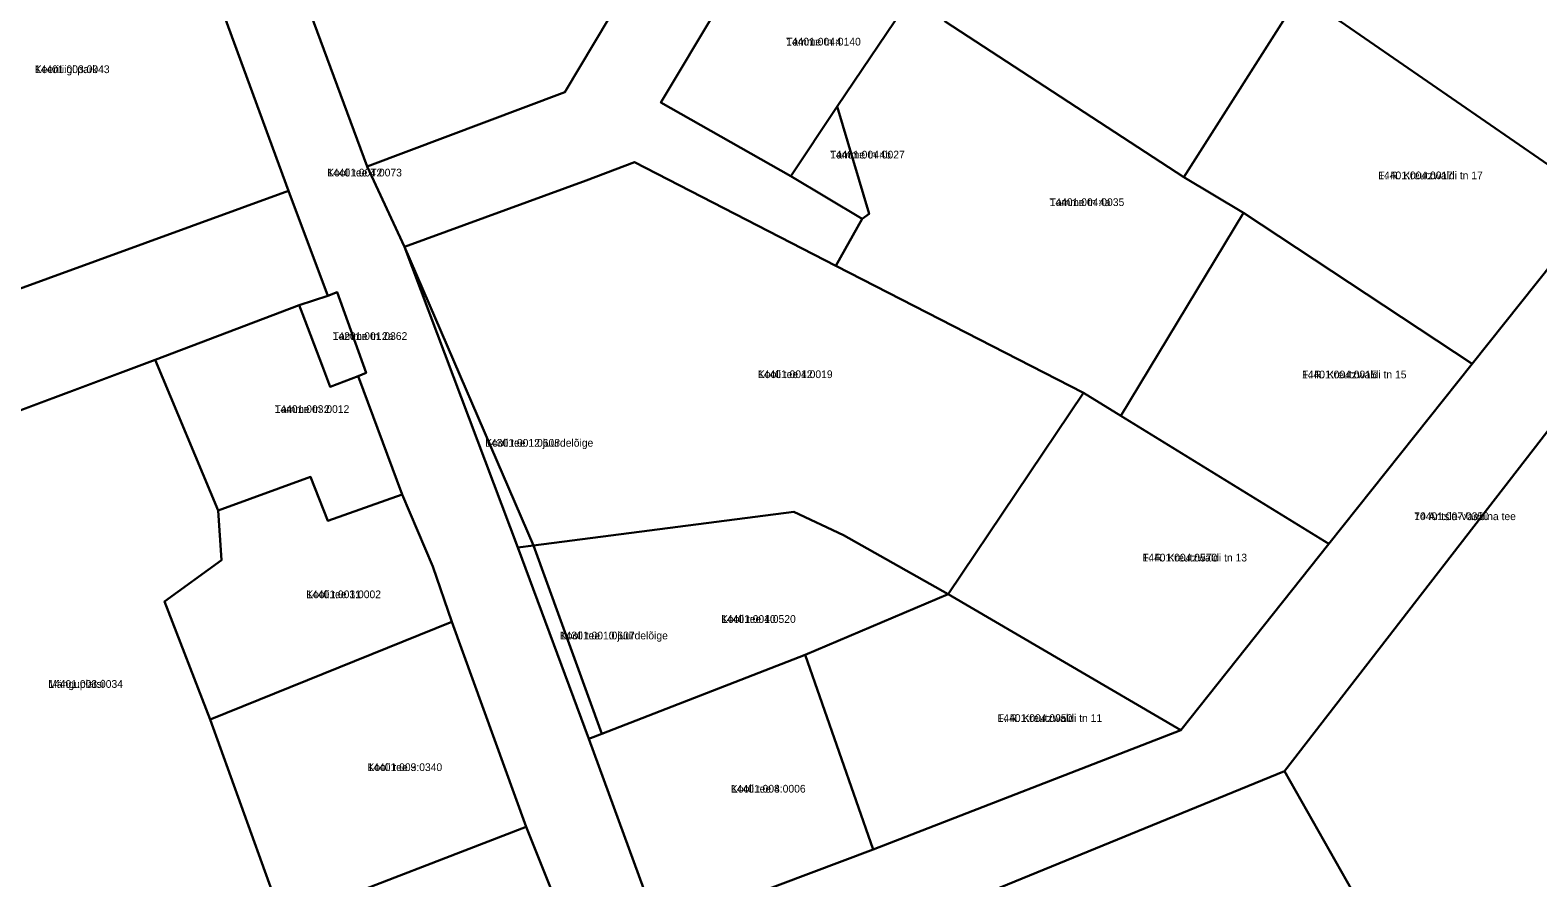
# Model space of a CAD drawing. Extents: x 640657 to 665127, y 6395726 to 6426831.
# Drawn here: x 650279.6 to 650572.3, y 6412630.2 to 6412794.8 of the extents above; entities that cross this region are included whole.
import ezdxf

# ---------------------------------------------------------------- set-up
doc = ezdxf.new("R2010")
doc.units = 0
for name, color, linetype in [('L_AADRESS', 7, 'Continuous'), ('PIIR', 7, 'Continuous'), ('TUNNUS', 7, 'Continuous')]:
    doc.layers.add(name, color=color, linetype=linetype)

msp = doc.modelspace()

# ---------------------------------------------------------------- linework, layer by layer
at = {"layer": 'PIIR'}
for points in [[(650401.68, 6412620.02), (650443.31, 6412635.66), (650502.99, 6412658.87), (650531.76, 6412695.05), (650559.55, 6412729.99), (650584.65, 6412761.55), (650611.45, 6412796.26), (650628.07, 6412817.98), (650642.14, 6412836.53), (650659.43, 6412858.77), (650671.35, 6412873.26), (650691.08, 6412899.24), (650704.96, 6412917.1), (650717.93, 6412933.8), (650741.65, 6412963.62), (650765.03, 6412993.85), (650786.55, 6413021.63), (650809.09, 6413051.96), (650817.6, 6413061.15)], [(650817.7, 6413031.91), (650806.76, 6413017.69), (650784.43, 6412989.36), (650760.68, 6412958.63), (650735.21, 6412925.98), (650707.5, 6412890.28), (650682.06, 6412857.34), (650670.16, 6412841.93), (650650.26, 6412816.25), (650622.9, 6412780.36), (650600.95, 6412752.04), (650584, 6412729.6), (650523.13, 6412650.87), (650462.26, 6412625.96)], [(650278.55, 6412923.91), (650292.03, 6412907.35), (650296.86, 6412894.32), (650296.86, 6412889.11), (650305.95, 6412866.72), (650311.87, 6412858.01), (650345.05, 6412768.31), (650352.3, 6412752.69), (650374.32, 6412694.32), (650388.11, 6412657.18), (650401.68, 6412620.02)], [(650386.32, 6412614.06), (650375.93, 6412640.11), (650361.5, 6412679.88), (650357.8, 6412690.63), (650351.84, 6412704.65), (650343.32, 6412727.61), (650344.83, 6412728.23), (650339.2, 6412743.9), (650337.4, 6412743.2), (650329.8, 6412763.6), (650299.3, 6412846.7), (650285.9, 6412881.2), (650282.26, 6412886.17), (650272.9, 6412909.24)], [(650424.35, 6412817.94), (650402.06, 6412780.76), (650427.29, 6412766.46), (650441.14, 6412758.16), (650436.06, 6412749.03), (650396.96, 6412769.19), (650387.58, 6412765.59), (650352.3, 6412752.69), (650345.05, 6412768.31), (650383.45, 6412782.73), (650417.77, 6412840.38)]]:
    msp.add_lwpolyline(points, dxfattribs=at)
for points in [[(650417.77, 6412840.38), (650383.45, 6412782.73), (650345.05, 6412768.31), (650311.87, 6412858.01), (650305.95, 6412866.72), (650296.86, 6412889.11), (650296.86, 6412894.32), (650338.71, 6412906.62), (650358.95, 6412912.76), (650376.75, 6412903.52), (650390.5, 6412895.83), (650400.6, 6412893.6), (650403.65, 6412886.89), (650408.31, 6412875.93), (650410.14, 6412871.67), (650407.97, 6412866.46)], [(650208.51, 6412773.92), (650218.79, 6412778), (650277.53, 6412801.82), (650264.5, 6412831.05), (650282.69, 6412839.36), (650299.3, 6412846.7), (650329.8, 6412763.6), (650227.2, 6412726.23), (650217.94, 6412750.3)], [(650455.48, 6412798.05), (650483.2, 6412840.21), (650493.55, 6412833.51), (650526.12, 6412801.71), (650503.6, 6412766.24), (650457.28, 6412796.49)], [(650534.02, 6412796.48), (650562.63, 6412831.16), (650565.69, 6412829.54), (650611.45, 6412796.26), (650584.65, 6412761.55)], [(650427.29, 6412766.46), (650402.06, 6412780.76), (650424.35, 6412817.94), (650450.69, 6412801.37), (650436.3, 6412779.95)], [(650559.55, 6412729.99), (650515.2, 6412759.31), (650503.6, 6412766.24), (650526.12, 6412801.71), (650534.02, 6412796.48), (650584.65, 6412761.55)], [(650450.69, 6412801.37), (650455.48, 6412798.05), (650457.28, 6412796.49), (650503.6, 6412766.24), (650515.2, 6412759.31), (650491.34, 6412719.91), (650484.11, 6412724.36), (650436.06, 6412749.03), (650441.14, 6412758.16), (650442.52, 6412759.16), (650436.3, 6412779.95)], [(650436.3, 6412779.95), (650442.52, 6412759.16), (650441.14, 6412758.16), (650427.29, 6412766.46)], [(650377.32, 6412694.73), (650352.3, 6412752.69), (650387.58, 6412765.59), (650396.96, 6412769.19), (650436.06, 6412749.03), (650484.11, 6412724.36), (650457.84, 6412685.26), (650437.49, 6412696.74), (650427.87, 6412701.23)], [(650172.47, 6412706.22), (650227.2, 6412726.23), (650329.8, 6412763.6), (650337.4, 6412743.2), (650331.86, 6412741.39), (650303.9, 6412730.8), (650237.7, 6412706), (650178.71, 6412684.02)], [(650531.76, 6412695.05), (650491.34, 6412719.91), (650515.2, 6412759.31), (650559.55, 6412729.99)], [(650374.32, 6412694.32), (650352.3, 6412752.69), (650377.32, 6412694.73)], [(650331.86, 6412741.39), (650337.4, 6412743.2), (650339.2, 6412743.9), (650344.83, 6412728.23), (650343.32, 6412727.61), (650337.87, 6412725.54), (650336.3, 6412729.66), (650332.48, 6412739.7)], [(650331.86, 6412741.39), (650332.48, 6412739.7), (650336.3, 6412729.66), (650337.87, 6412725.54), (650343.32, 6412727.61), (650351.84, 6412704.65), (650337.41, 6412699.52), (650334.07, 6412708.04), (650316.1, 6412701.52), (650303.88, 6412730.75)], [(650237.63, 6412705.98), (650303.88, 6412730.75), (650316.1, 6412701.52), (650316.75, 6412691.86), (650305.68, 6412683.87), (650314.59, 6412660.95), (650328.64, 6412621.96), (650285.03, 6412605.8), (650278.75, 6412623.58), (650267.2, 6412619.43), (650265.16, 6412625.12), (650252.6, 6412662.9)], [(650523.13, 6412650.87), (650584, 6412729.6), (650615.4, 6412688.3), (650658.1, 6412630.7), (650574.96, 6412560.92), (650573.52, 6412570.41), (650550.64, 6412602.33)], [(650457.84, 6412685.26), (650484.11, 6412724.36), (650491.34, 6412719.91), (650531.76, 6412695.05), (650502.99, 6412658.87)], [(650316.1, 6412701.52), (650334.07, 6412708.04), (650337.41, 6412699.52), (650351.84, 6412704.65), (650357.8, 6412690.63), (650361.5, 6412679.88), (650314.59, 6412660.95), (650305.68, 6412683.87), (650316.75, 6412691.86)], [(650377.32, 6412694.73), (650427.87, 6412701.23), (650437.49, 6412696.74), (650457.84, 6412685.26), (650430.06, 6412673.47), (650390.59, 6412658.16)], [(650388.11, 6412657.18), (650374.32, 6412694.32), (650377.32, 6412694.73), (650390.59, 6412658.16)], [(650457.84, 6412685.26), (650502.99, 6412658.87), (650443.31, 6412635.66), (650430.06, 6412673.47)], [(650331.99, 6412623.16), (650328.64, 6412621.96), (650314.59, 6412660.95), (650361.5, 6412679.88), (650375.93, 6412640.11)], [(650401.68, 6412620.02), (650388.11, 6412657.18), (650390.59, 6412658.16), (650430.06, 6412673.47), (650443.31, 6412635.66)], [(650523.13, 6412650.87), (650550.64, 6412602.33), (650510.67, 6412584.89), (650484.84, 6412573.61), (650473.06, 6412600.93), (650462.26, 6412625.96)], [(650375.93, 6412640.11), (650386.32, 6412614.06), (650340.27, 6412596.89), (650331.99, 6412623.16)]]:
    msp.add_lwpolyline(points, close=True, dxfattribs=at)

# ---------------------------------------------------------------- texts
at = {"layer": 'L_AADRESS'}
for s, p in [('Tamme tn 4', (650426.38, 6412791.82)), ('Keeritiigi park', (650280.54, 6412786.46)), ('Tamme tn 4b', (650434.91, 6412769.88)), ('Kooli tee T2', (650337.29, 6412766.39)), ('F. R. Kreutzwaldi tn 17', (650541.34, 6412765.85)), ('Tamme tn 4a', (650477.53, 6412760.64)), ('Tamme tn 2a', (650338.34, 6412734.64)), ('Kooli tee 12', (650420.91, 6412727.23)), ('F. R. Kreutzwaldi tn 15', (650526.53, 6412727.18)), ('Tamme tn 2', (650327.08, 6412720.46)), ('Kooli tee 12 juurdelõige', (650367.98, 6412713.91)), ('70 Antsla-Vaabina tee', (650548.32, 6412699.65)), ('F. R. Kreutzwaldi tn 13', (650495.57, 6412691.62)), ('Kooli tee 11', (650333.23, 6412684.49)), ('Kooli tee 10', (650413.75, 6412679.7)), ('Kooli tee 10 juurdelõige', (650382.46, 6412676.49)), ('Mänguplatsi', (650283.14, 6412667.08)), ('F. R. Kreutzwaldi tn 11', (650467.44, 6412660.46)), ('Kooli tee 9', (650345.11, 6412650.92)), ('Kooli tee 8', (650415.67, 6412646.74))]:
    msp.add_text(s, height=1.5, dxfattribs=at).set_placement(p)
at = {"layer": 'TUNNUS'}
for s, p in [('14401:004:0140', (650426.38, 6412791.82)), ('14401:003:0043', (650280.54, 6412786.46)), ('14401:004:0027', (650434.91, 6412769.88)), ('14401:004:0073', (650337.29, 6412766.39)), ('14401:004:0017', (650541.34, 6412765.85)), ('14401:004:0035', (650477.53, 6412760.64)), ('14201:001:0362', (650338.34, 6412734.64)), ('14401:004:0019', (650420.91, 6412727.23)), ('14401:004:0015', (650526.53, 6412727.18)), ('14401:003:0012', (650327.08, 6412720.46)), ('14301:001:0608', (650367.98, 6412713.91)), ('14401:007:0350', (650548.32, 6412699.65)), ('14401:004:0570', (650495.57, 6412691.62)), ('14401:003:0002', (650333.23, 6412684.49)), ('14401:004:0520', (650413.75, 6412679.7)), ('14301:001:0607', (650382.46, 6412676.49)), ('14401:003:0034', (650283.14, 6412667.08)), ('14401:004:0050', (650467.44, 6412660.46)), ('14401:003:0340', (650345.11, 6412650.92)), ('14401:004:0006', (650415.67, 6412646.74))]:
    msp.add_text(s, height=1.5, dxfattribs=at).set_placement(p)

doc.saveas('drawing.dxf')
